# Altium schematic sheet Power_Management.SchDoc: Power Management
size A4; Date: Not used; ApprovedBy: Not used; CheckedBy: Not used; Author: Not used; CompanyName: STMicroelectronics; DrawnBy: Not used; Engineer: Not used; Organization: Not used; Address1: Not used; Address2: Not used; Address3: Not used; Address4: Not used; DocumentNumber: Not used; Revision: Not used; SheetNumber: 5; SheetTotal: 7
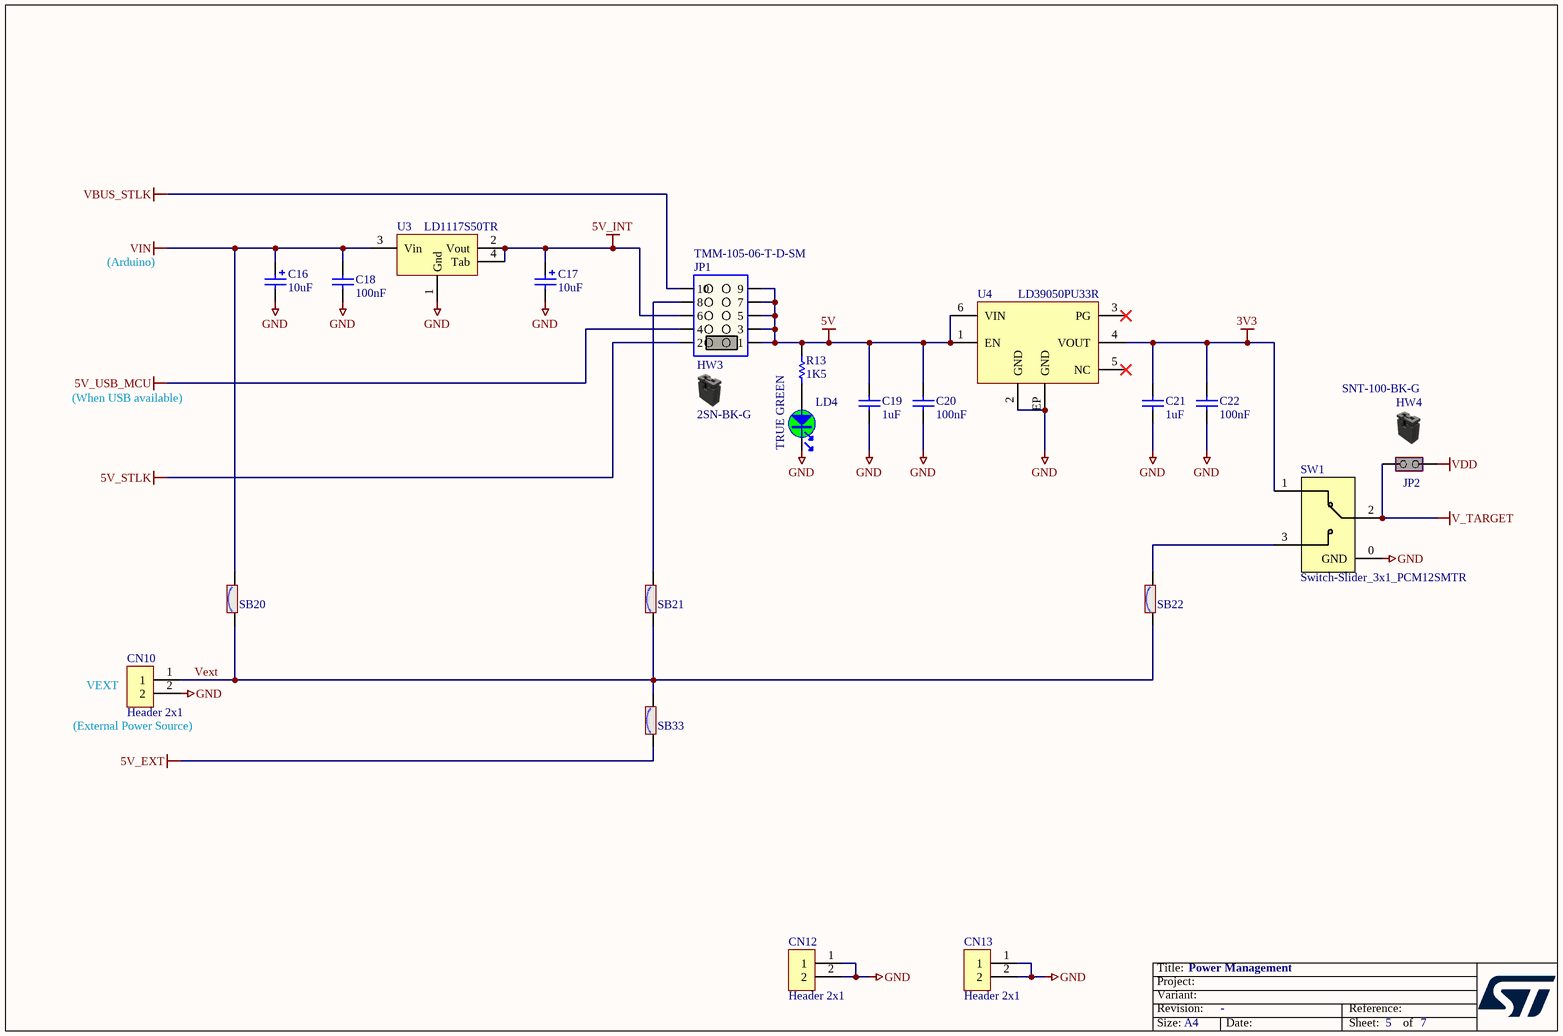
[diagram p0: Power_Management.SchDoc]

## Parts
C16  value 10uF  [CPOL_TAJ-B_1210_H210]  (hidden comment: Cap_POL_TANA)
C17  value 10uF  [CPOL_TAJ-B_1210_H210]  (hidden comment: Cap_POL_TANA)
C18  value 100nF  [C0402]  (hidden comment: Capacitor)
C19  value 1uF  [C0805_H0P85]  (hidden comment: Capacitor)
C20  value 100nF  [C0402]  (hidden comment: Capacitor)
C21  value 1uF  [C0805_H0P85]  (hidden comment: Capacitor)
C22  value 100nF  [C0402]  (hidden comment: Capacitor)
CN10  Header 2x1  [CON_SAMTEC_TSW-102-07-G-S]
CN12  Header 2x1  [CON_SAMTEC_TSW-102-07-G-S]
CN13  Header 2x1  [CON_SAMTEC_TSW-102-07-G-S]
HW3  2SN-BK-G  (mechanical)
HW4  value SNT-100-BK-G  (hidden comment: Shunt Black 2.54mm)  (mechanical)
JP1  value TMM-105-06-T-D-SM  [CON_SAMTEC_TMM-105-06-T-D-SM]  (hidden comment: Jumper 5 Positions)
JP2  Jumper_Header 2x1 Fitted  [CON_SAMTEC_TSW-102-07-G-S]  (value not drawn)
LD4  value TRUE GREEN  [LED_0603_VISHAY_VLMTG1300-GS08_GREEN_1A2K_H0P8]  (hidden comment: LED_green)
R13  value 1K5  [R0402]  (hidden comment: Resistor)
SB20  SB_ON  [SOLDER-BRIDGE_R0402-0R]  (value not drawn)
SB21  SB_ON  [SOLDER-BRIDGE_R0402-0R]  (value not drawn)
SB22  SB_ON  [SOLDER-BRIDGE_R0402-0R]  (value not drawn)
SB33  SB_ON  [SOLDER-BRIDGE_R0402-0R]  (value not drawn)
SW1  value Switch-Slider_3x1_PCM12SMTR  [SWI_SPDT-RA_TE-CONNECTIVITY_MLL1200S_1P2T]  (hidden comment: SW_MECA)
U3  LD1117S50TR  [REG_SOT223-TAB]
U4  LD39050PU33R  [ICC_DFN6-EPAD_3X3_P095]

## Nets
3V3: C21.2 C22.2 SW1.1 U4.4(VOUT)
5V: C19.2 C20.2 JP1.1 JP1.3 JP1.5 JP1.7 JP1.9 R13.2 U4.1(EN) U4.6(VIN)
5V_EXT: SB33.1
5V_INT: C17.1 JP1.6 U3.2(Vout) U3.4(Tab)
5V_STLK: JP1.2
5V_USB_MCU: JP1.4
GND: C16.2 C17.2 C18.1 C19.1 C20.1 C21.1 C22.1 CN10.2 CN12.1 CN12.2 CN13.1 CN13.2 LD4.2 SW1.0(GND) U3.1(Gnd) U4.2(GND) U4.EP(GND)
V_TARGET: JP2.1(COMMON) SW1.2
VBUS_STLK: JP1.10
VDD: JP2.2(NO)
VIN: C16.1 C18.2 SB20.2 U3.3(Vin)
Vext: CN10.1 SB20.1 SB21.1 SB22.1 SB33.2
NetJP1_8: JP1.8 SB21.2
NetLD4_1: LD4.1 R13.1
NetSB22_2: SB22.2 SW1.3

Not connected (* = marked no-connect by the designer): U4 3(PG)* 5(NC)*

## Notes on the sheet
- (Arduino)
- (When USB available)
- (near CN10) VEXT
- (near CN10) (External Power Source)

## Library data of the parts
C16 C17 = MCD-00324: Capacitor, Tantalum, 10uF, 25V, 2R5, +/-10%, Type_B (3528 metric), T=1.9mm; Manufacturer_Part_Number: TAJB106K025RNJ; Manufacturer: AVX; Part_Preference: Recommended; Order_Code_RS: 136-0159; Component_Country_Of_Origin: El Salvador
C18 C20 C22 = MCD-02355: Capacitor, MLCC, 100nF, 25V, X7R, +/-10%, 0402, T=0.5mm; Part_Preference: Recommended; Manufacturer: WALSIN; Manufacturer_Part_Number: 0402B104K250CT; Order_Code_RS: 176-3114; Component_Country_Of_Origin: Unknown
C19 C21 = MCD-01550: Capacitor, MLCC, 1uF, 16V, X5R, +/-10%, 0805, T=0.85mm; Manufacturer_Part_Number: CC0805KRX5R7BB105; Manufacturer: YAGEO; Part_Preference: Recommended; Component_Country_Of_Origin: China
CN10 CN12 CN13 = MCD-00032: Header, 2x1, 2.54mm, VR, TH, T=5.84mm/2.54mm; Part_Type: Connector; Part_Preference: Recommended; Manufacturer: SAMTEC; Manufacturer_Part_Number: TSW-102-07-G-S; Order_Code_RS: 155-5312; Component_Country_Of_Origin: China, Costa Rica, Malaysia, United States, Vietnam
HW3 = MCD-03319: Shunt, 2,00mm, black; Part_Type: Connector; Part_Preference: Recommended; Manufacturer: SAMTEC; Full_Alternate_Internal_Part_Number: CHERNG-WEEI_CMJ-20AB; Order_code_RS: 159-3178; ShowFields: YES; ID: 5435
HW4 = MCD-00043: SHUNT 2.54mm BLACK; Part_Type: Misc; Manufacturer: SAMTEC; Part_Preference: Recommended; Alternate_Internal_Part_Number: MCD-02388; Component_Country_Of_Origin: China, Costa Rica, Malaysia, United States, Vietnam
JP1 = MCD-03317: Header, 10x2, 2,00mm, h=7,04mm, VR, SMD; Part_Type: Connector; Part_Preference: Recommended; Manufacturer: SAMTEC; Full_Alternate_Internal_Part_Number: CHERNG-WEEI_P401-MG4GN-0404-10-R; ShowFields: YES; ID: 5433
JP2 = MCD-01904: Header, 2x1, 2.54mm, VR, TH, T=5.84mm/2.54mm; Part_Type: Connector; Manufacturer_Part_Number: TSW-102-07-G-S; Manufacturer: SAMTEC; Part_Preference: Recommended; Order_Code_RS: 155-7981; Component_Country_Of_Origin: China, Costa Rica, Malaysia, United States, Vietnam
LD4 = MCD-00589: LED Green, 0603 SMD, Fw Voltage = 2.8V - 3.6V; Part_Type: Display; Manufacturer_Part_Number: VLMTG1300-GS08; Manufacturer: VISHAY; Part_Preference: Recommended; Order_Code_RS: 7730452; Component_Country_Of_Origin: China
R13 = MCD-00068: Resistor, 1K5, 0402, +/-1%, 1/16W; Part_Preference: Recommended; Manufacturer: YAGEO; Manufacturer_Part_Number: RC0402FR-071K5L; Component_Country_Of_Origin: China; ShowFields: YES; ID: 2524
SB20-SB22 SB33 = MCD-01618: Solder Bridge 0402 ON; Part_Type: Misc; Part_Preference: Recommended; Manufacturer: YAGEO; Manufacturer_Part_Number: RC0402JR-070RL; Order_Code_RS: 618-5804; Component_Country_Of_Origin: China
SW1 = MCD-03571: Slide switch, 3x1, 1.5mm, RA, SMT, T=1.65mm; Part_Type: Connector; Part_Preference: Recommended; Manufacturer: C&K; Manufacturer_Part_Number: PCM12SMTR; Order_Code_RS: 793-1721; ShowFields: YES; ID: 5687
U3 = MCD-00088: IC REG LDO 5V 0.8A SOT223; Manufacturer: STMICROELECTRONICS; BMS_Part_Number: 9176133; Part_Preference: Recommended; Manufacturer_HQ_COO: EU; Component_Country_Of_Origin: China
U4 = MCD-00215: Low quiescent current and low noise voltage regulators; Part_Type: IC; Manufacturer: STMICROELECTRONICS; BMS_Part_Number: 9176126; Part_Preference: Recommended; Manufacturer_HQ_COO: EU; Component_Country_Of_Origin: Malaysia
